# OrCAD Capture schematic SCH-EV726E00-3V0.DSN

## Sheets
1 Others: size C; title: EV726E00_Others; rev: 1.0; note: <Doc>
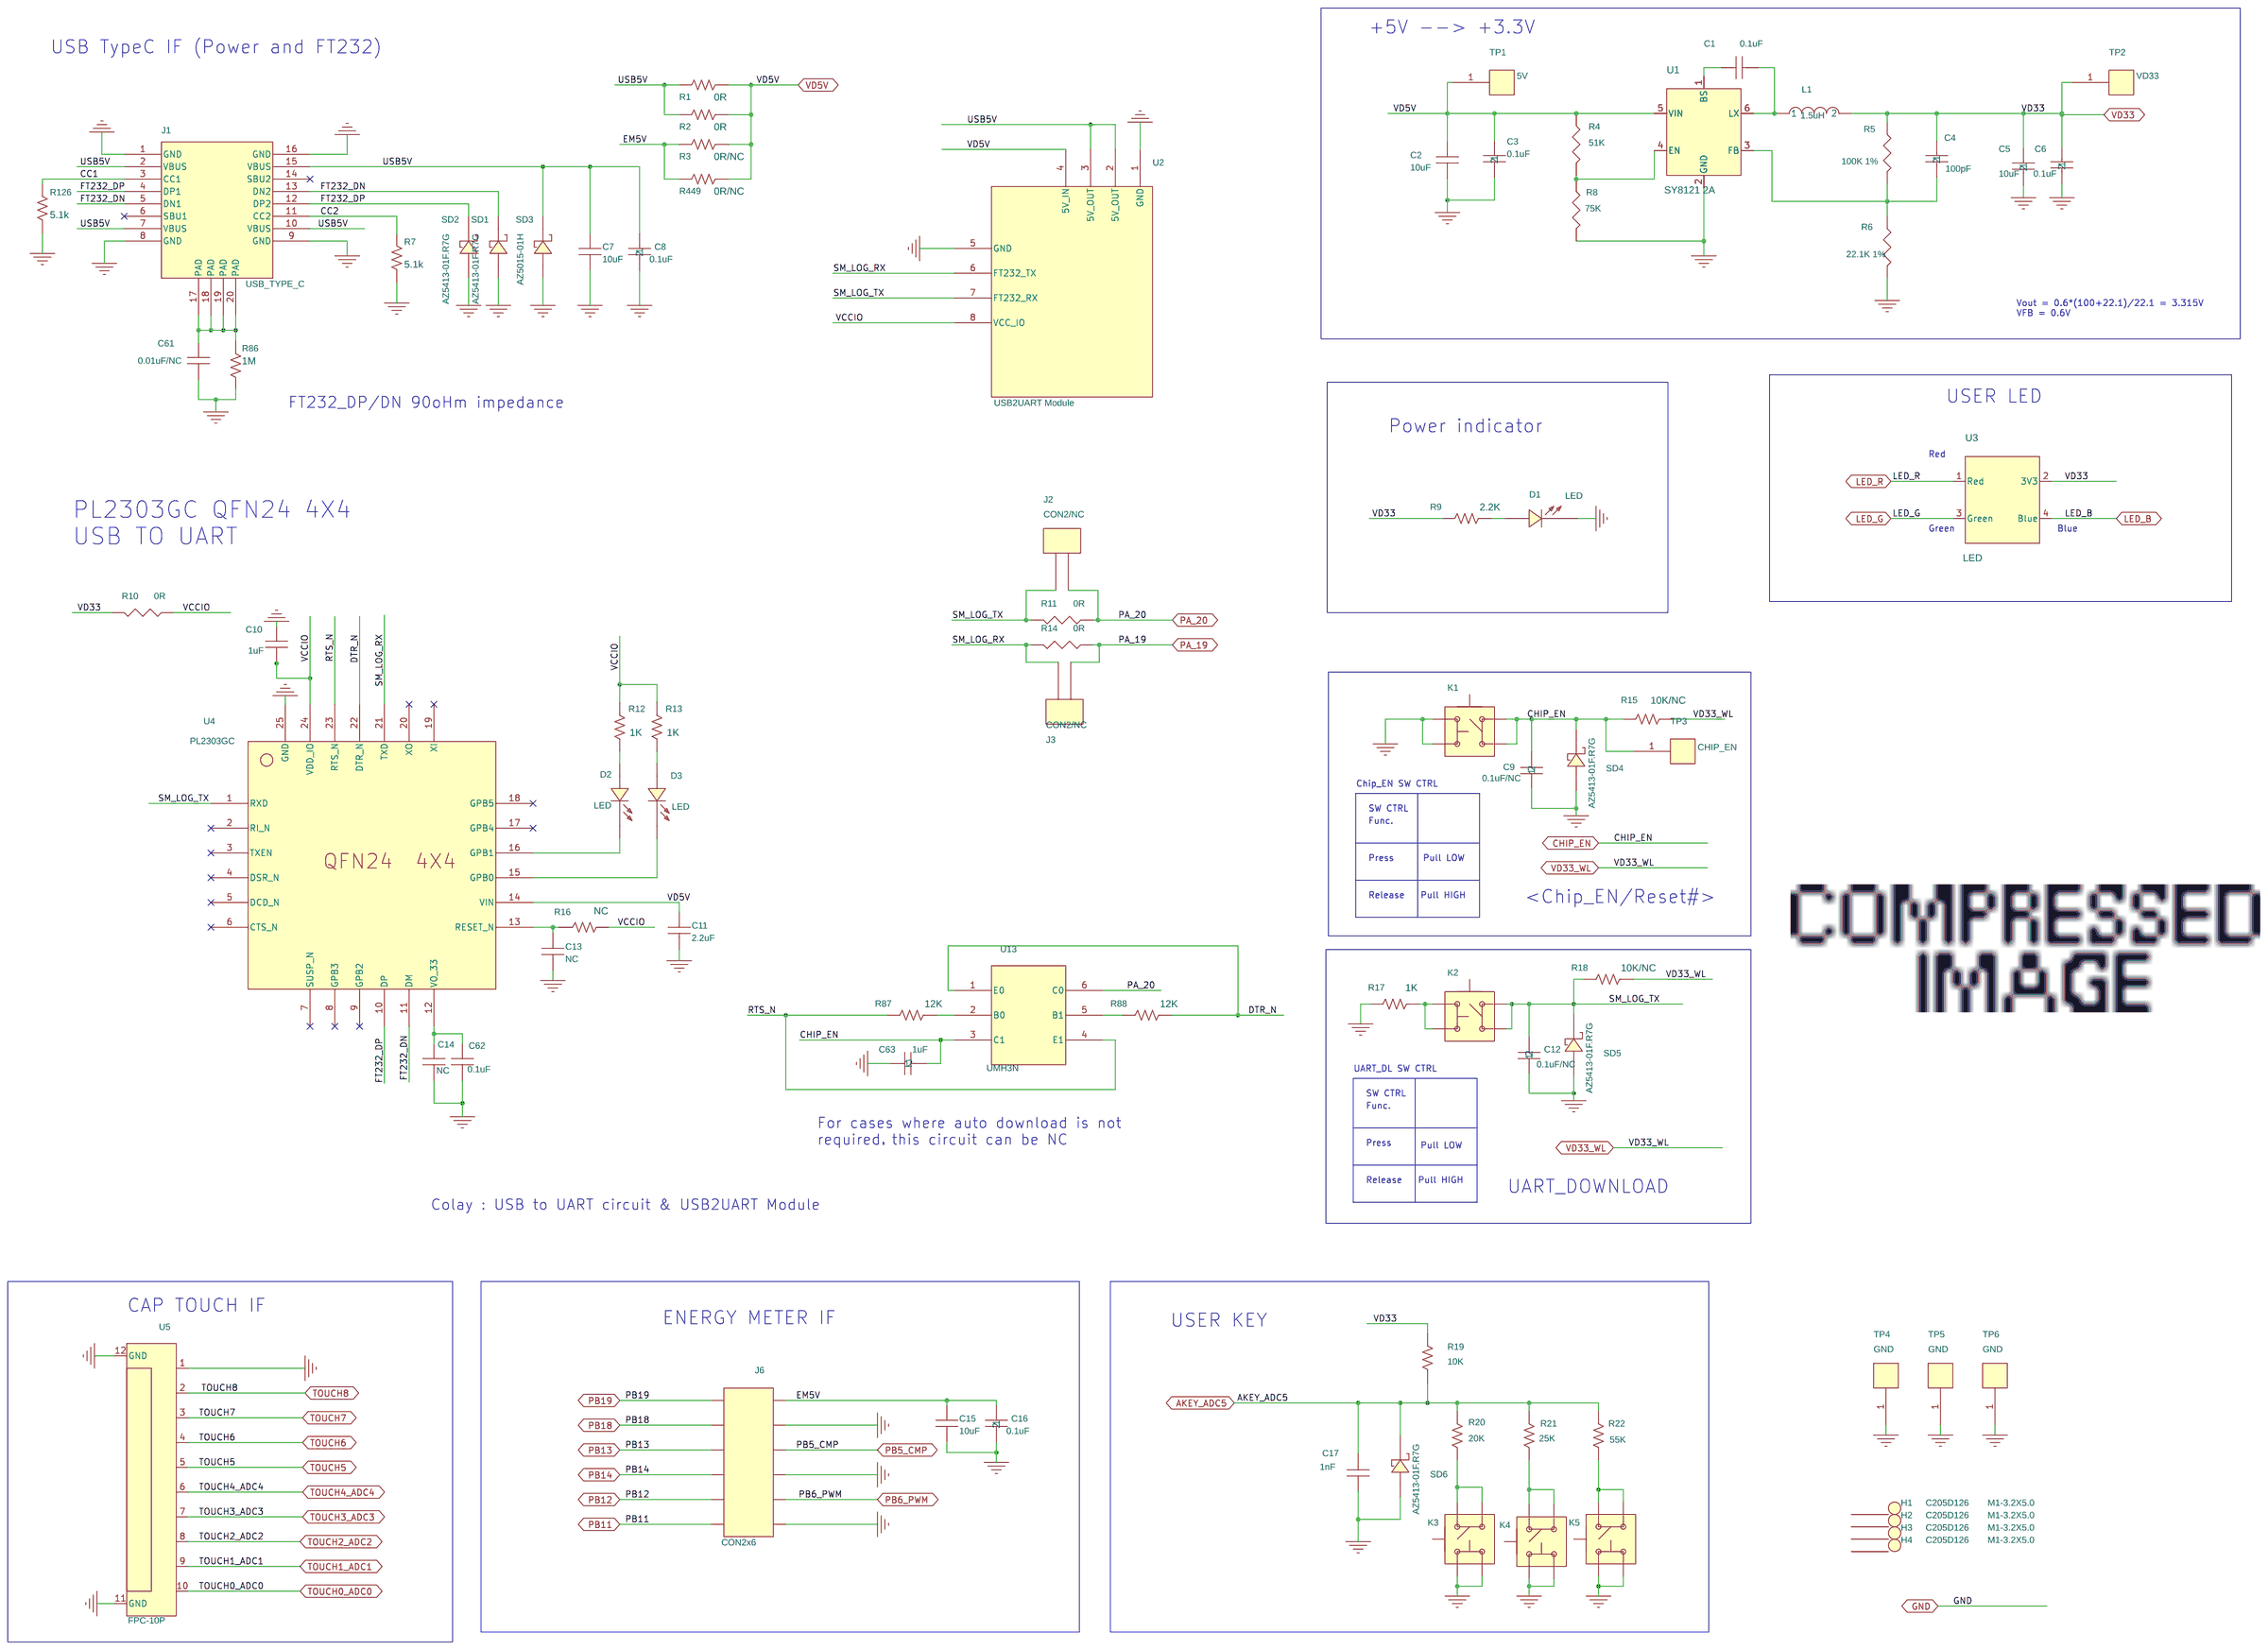
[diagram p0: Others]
2 SMPF: size C; title: EV726E00
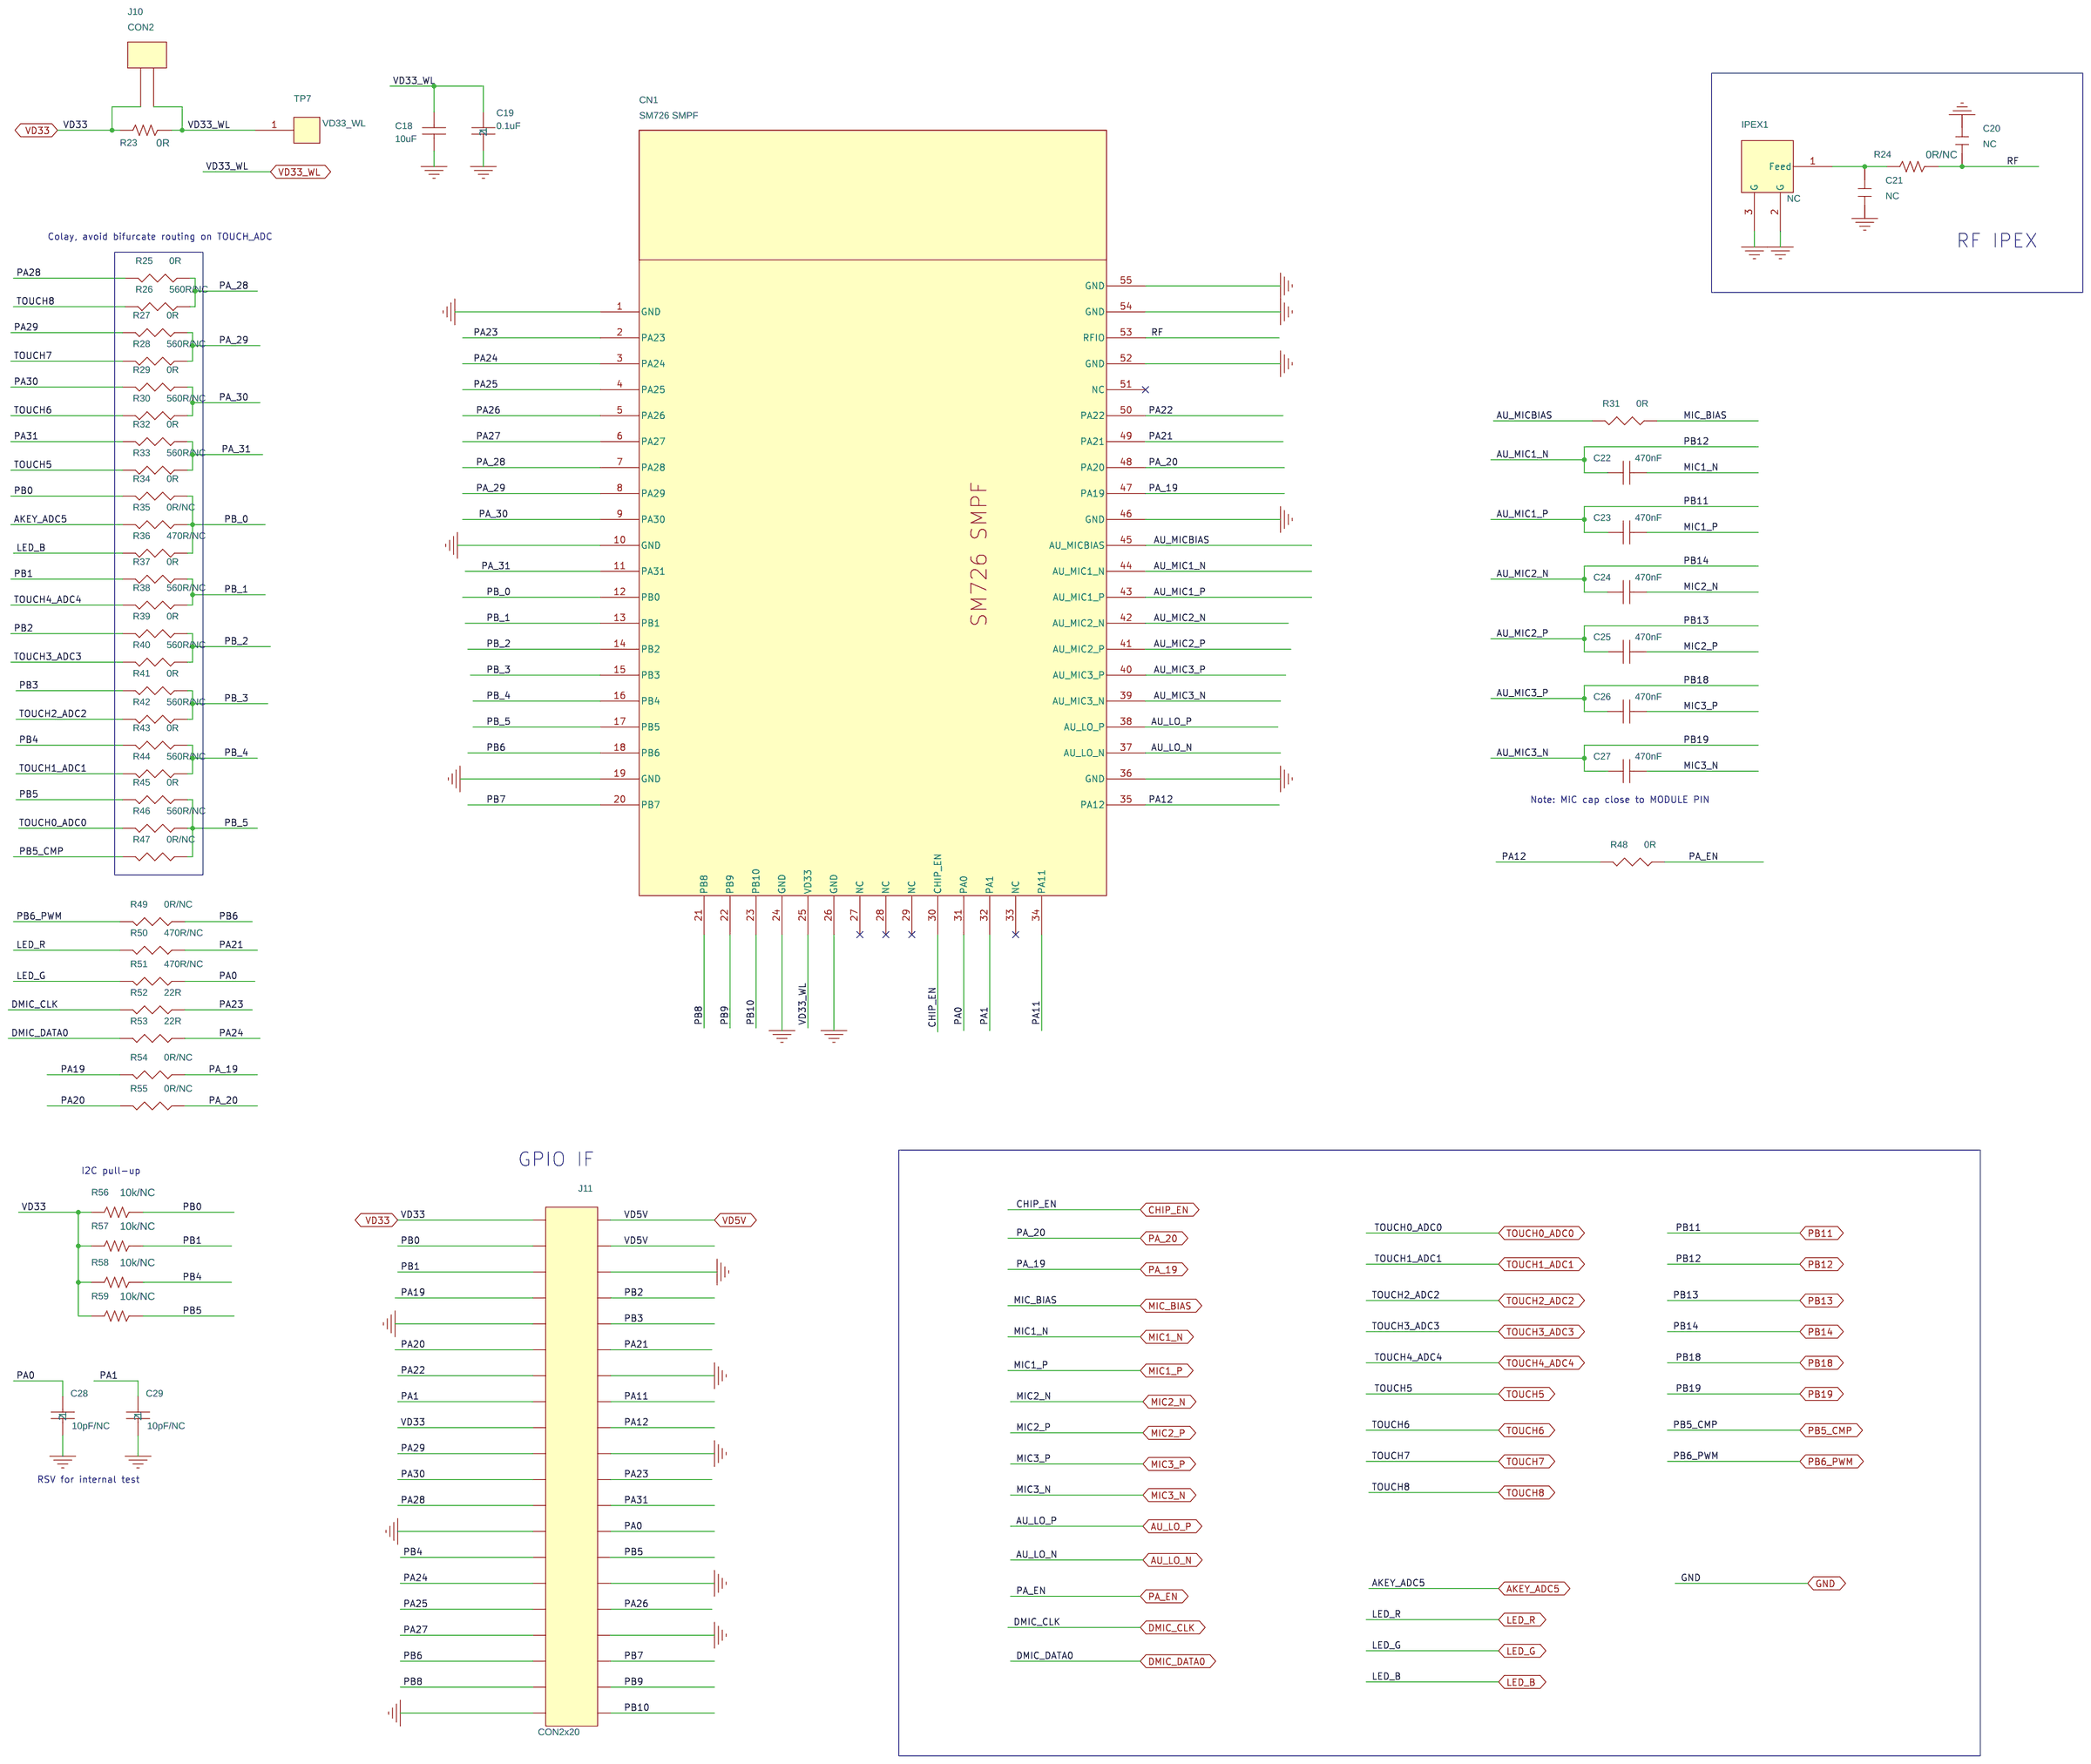
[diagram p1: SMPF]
3 Audio: size C; title: EV726E00_Audio
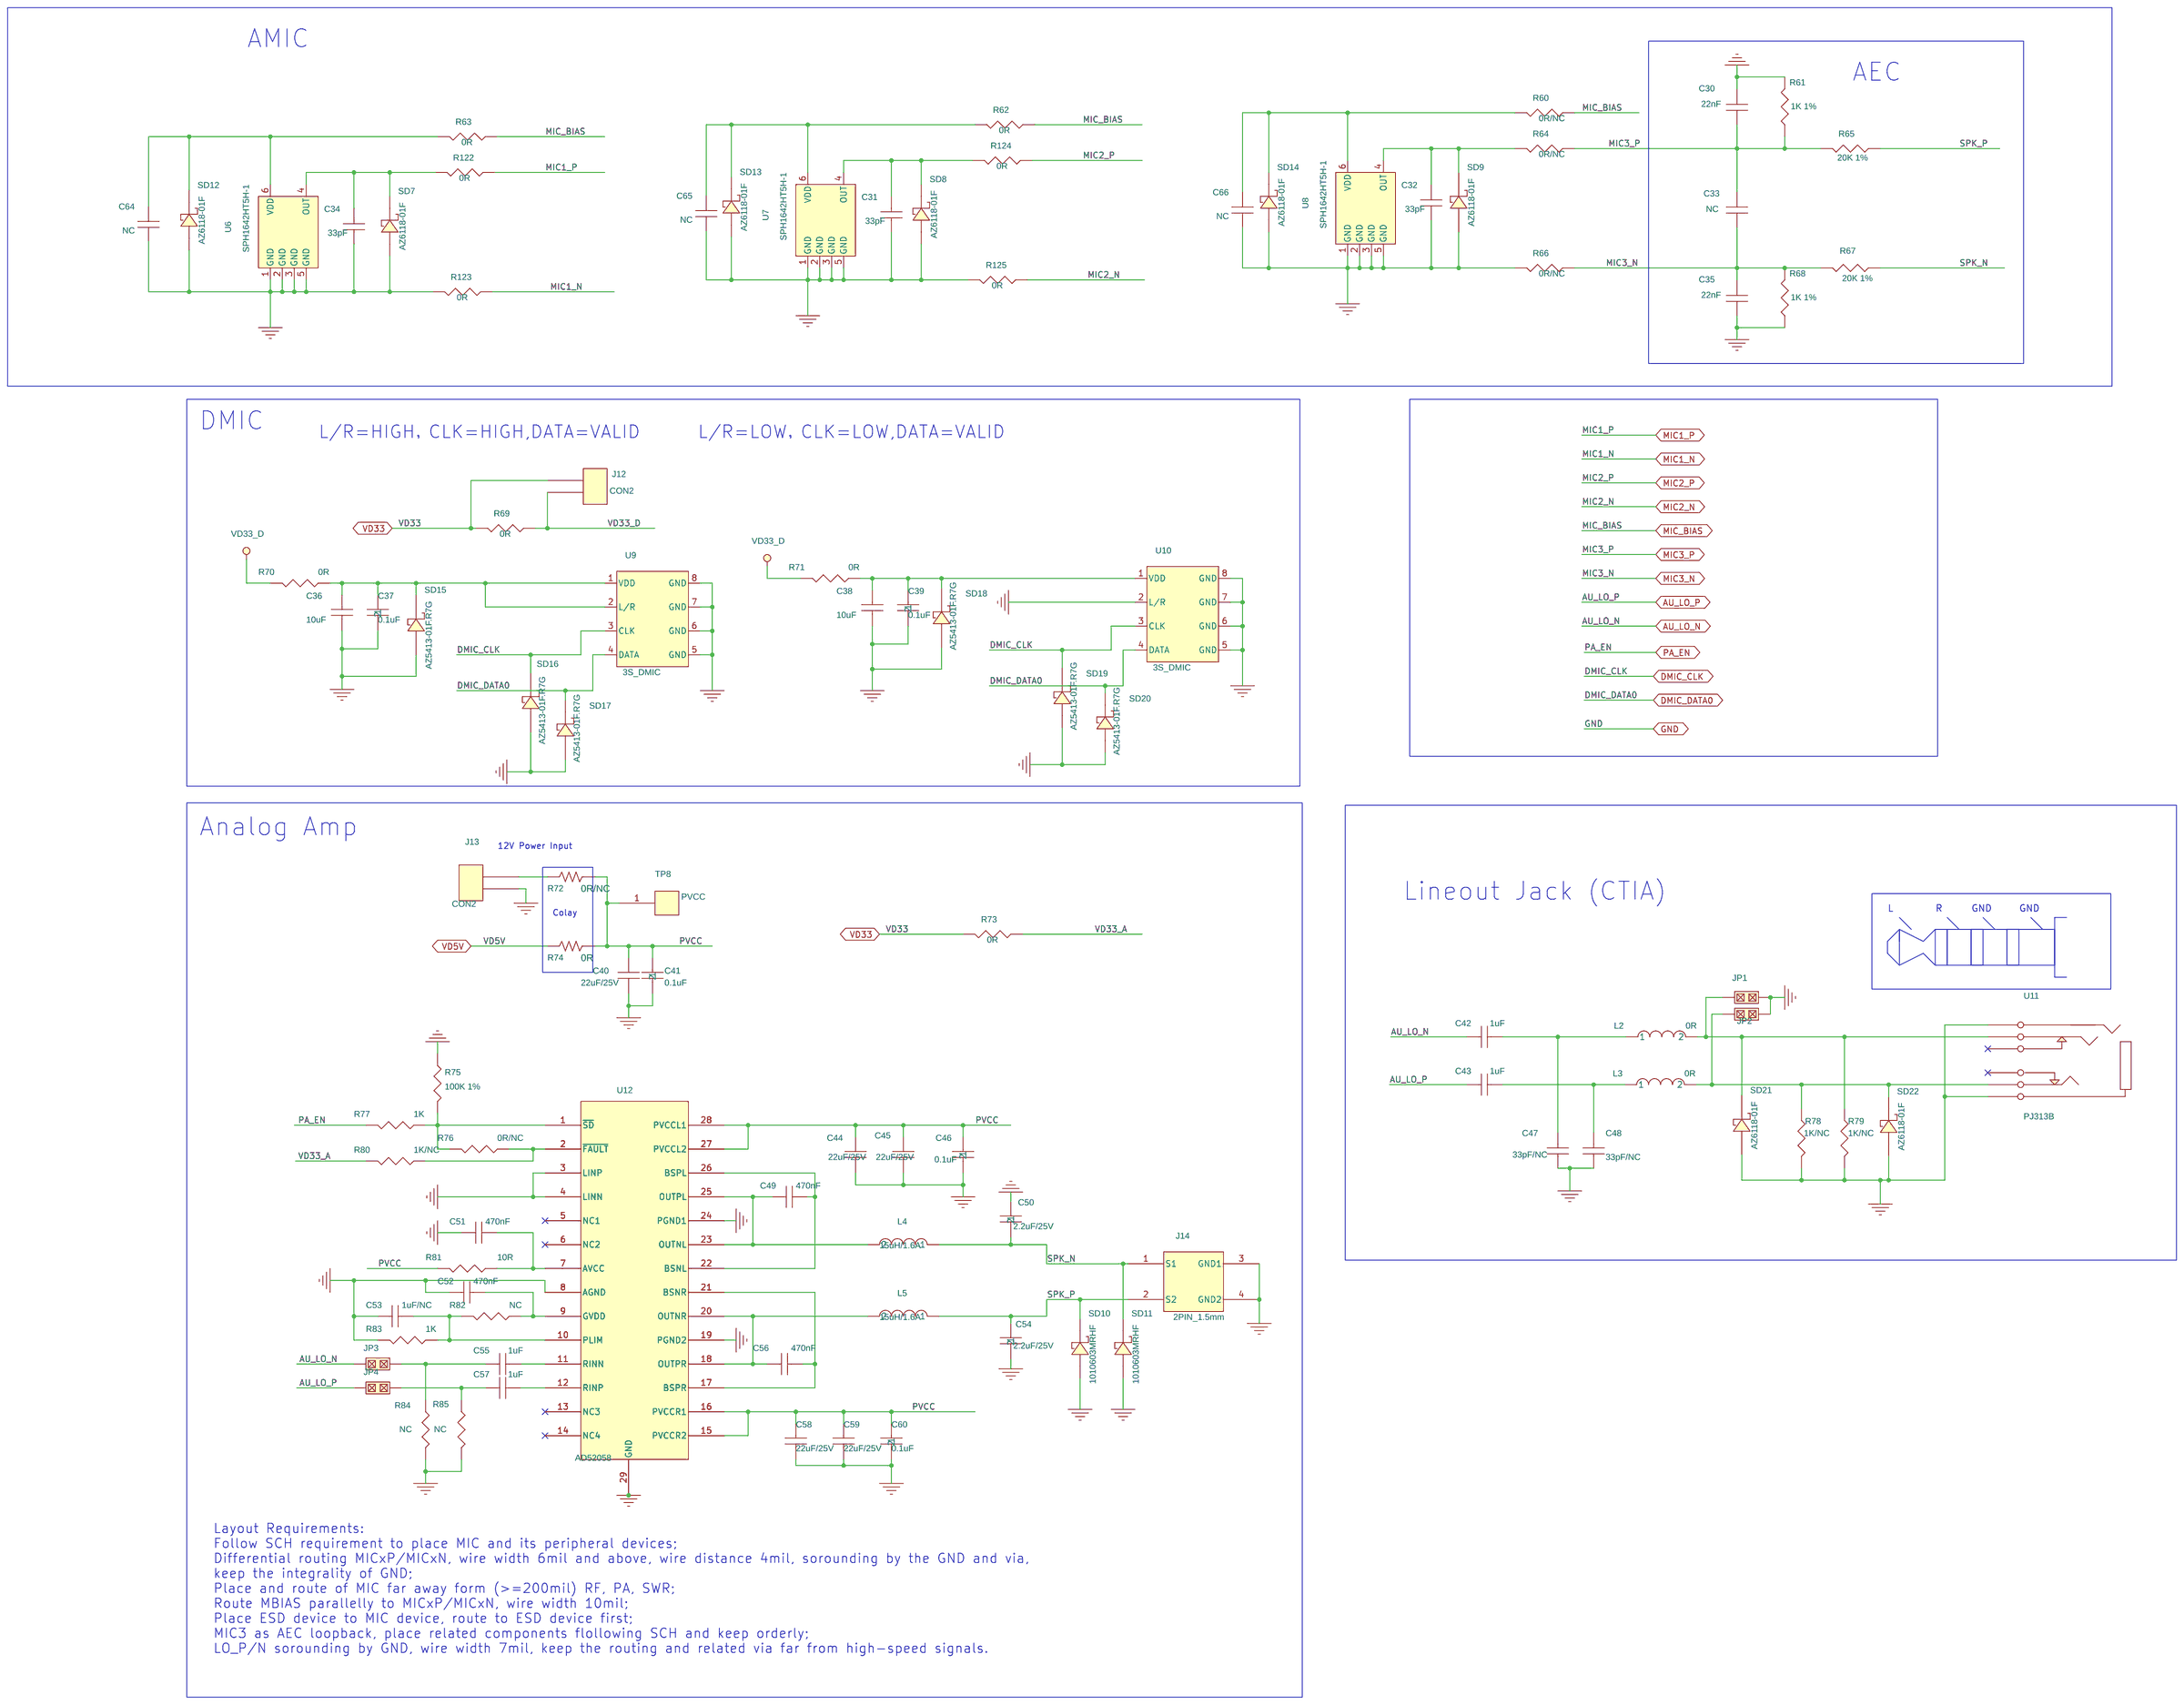
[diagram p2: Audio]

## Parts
sheet Audio
C30  22nF  [C0402]
C31  33pF  [C0402]
C32  33pF  [C0402]
C33  NC  [C0402]
C34  33pF  [C0402]
C35  22nF  [C0402]
C36  10uF  [C0603]
C37  0.1uF  [C0402]
C38  10uF  [C0603]
C39  0.1uF  [C0402]
C40  22uF/25V  [C0805]
C41  0.1uF  [C0402]
C42  1uF  [C0402]
C43  1uF  [C0402]
C44  22uF/25V  [C0805]
C45  22uF/25V  [C0805]
C46  0.1uF  [C0402]
C47  33pF/NC  [C0402]
C48  33pF/NC  [C0402]
C49  470nF  [C0402]
C50  2.2uF/25V  [C0402]
C51  470nF  [C0402]
C52  470nF  [C0402]
C53  1uF/NC  [C0402]
C54  2.2uF/25V  [C0402]
C55  1uF  [C0402]
C56  470nF  [C0402]
C57  1uF  [C0402]
C58  22uF/25V  [C0805]
C59  22uF/25V  [C0805]
C60  0.1uF  [C0402]
C64  NC  [C0402]
C65  NC  [C0402]
C66  NC  [C0402]
J12  CON2  [SIP2-2.54]
J13  CON2  [SIP2-2.54]
J14  2PIN_1.5mm  [2PIN-1.5MM]
JP1  1X2PIN  [SIP2-2.54]
JP2  1X2PIN  [SIP2-2.54]
JP3  1X2PIN  [SIP2-2.54]
JP4  1X2PIN  [SIP2-2.54]
L2  0R  [L0603]
L3  0R  [L0603]
L4  15uH/1.6A  [L5050]
L5  15uH/1.6A  [L5050]
R60  0R/NC  [R0402]
R61  1K 1%  [R0402]
R62  0R  [R0402]
R63  0R  [R0402]
R64  0R/NC  [R0402]
R65  20K 1%  [R0402]
R66  0R/NC  [R0402]
R67  20K 1%  [R0402]
R68  1K 1%  [R0402]
R69  0R  [R0402]
R70  0R  [R0402]
R71  0R  [R0402]
R72  0R/NC  [R0805]
R73  0R  [R0402]
R74  0R  [R0805]
R75  100K 1%  [R0402]
R76  0R/NC  [R0402]
R77  1K  [R0402]
R78  1K/NC  [R0402]
R79  1K/NC  [R0402]
R80  1K/NC  [R0402]
R81  10R  [R0402]
R82  NC  [R0402]
R83  1K  [R0402]
R84  NC  [R0402]
R85  NC  [R0402]
R122  0R  [R0402]
R123  0R  [R0402]
R124  0R  [R0402]
R125  0R  [R0402]
SD7  AZ6118-01F  [TVS-5413-6118-5451_DIR]
SD8  AZ6118-01F  [TVS-5413-6118-5451_DIR]
SD9  AZ6118-01F  [TVS-5413-6118-5451_DIR]
SD10  1010603MRHF  [TVS-5015-101060_DIR]
SD11  1010603MRHF  [TVS-5015-101060_DIR]
SD12  AZ6118-01F  [TVS-5413-6118-5451_DIR]
SD13  AZ6118-01F  [TVS-5413-6118-5451_DIR]
SD14  AZ6118-01F  [TVS-5413-6118-5451_DIR]
SD15  AZ5413-01F.R7G  [TVS-5413-6118-5451_DIR]
SD16  AZ5413-01F.R7G  [TVS-5413-6118-5451_DIR]
SD17  AZ5413-01F.R7G  [TVS-5413-6118-5451_DIR]
SD18  AZ5413-01F.R7G  [TVS-5413-6118-5451_DIR]
SD19  AZ5413-01F.R7G  [TVS-5413-6118-5451_DIR]
SD20  AZ5413-01F.R7G  [TVS-5413-6118-5451_DIR]
SD21  AZ6118-01F  [TVS-5413-6118-5451_DIR]
SD22  AZ6118-01F  [TVS-5413-6118-5451_DIR]
TP8  PVCC  [SIP-1P]
U6  SPH1642HT5H-1  [LGA]
U7  SPH1642HT5H-1  [LGA]
U8  SPH1642HT5H-1  [LGA]
U9  3S_DMIC  [3SM222FMT1KA]
U10  3S_DMIC  [3SM222FMT1KA]
U11  PJ313B  [AUDIO_JACK]
U12  AD52058  [E-TSSOP-28L]
sheet Others
C1  0.1uF  [C0402]
C2  10uF  [C0603]
C3  0.1uF  [C0402]
C4  100pF  [C0402]
C5  10uF  [C0603]
C6  0.1uF  [C0402]
C7  10uF  [C0603]
C8  0.1uF  [C0402]
C9  0.1uF/NC  [C0402]
C10  1uF  [C0402]
C11  2.2uF  [C0402]
C12  0.1uF/NC  [C0402]
C13  NC  [C0402]
C14  NC  [C0402]
C15  10uF  [C0603]
C16  0.1uF  [C0402]
C17  1nF  [C0402]
C61  0.01uF/NC  [C0402]
C62  0.1uF  [C0402]
C63  1uF  [C0603]
D1  LED  [LED-0603]
D2  LED  [LED-0603]
D3  LED  [LED-0603]
H1  C205D126  [M1-3.2X5.0]
H2  C205D126  [M1-3.2X5.0]
H3  C205D126  [M1-3.2X5.0]
H4  C205D126  [M1-3.2X5.0]
J1  USB_TYPE_C  [USB-C-SMT]
J2  CON2/NC  [SIP2-2.54]
J3  CON2/NC  [SIP2-2.54]
J6  CON2x6  [SIP6X2-2.54]
K1  Reset Button  [SW-4P-3X4]
K2  Reset Button  [SW-4P-3X4]
K3  Reset Button  [SW-4P-3X4]
K4  Reset Button  [SW-4P-3X4]
K5  Reset Button  [SW-4P-3X4]
L1  1.5uH  [MWSA0402]
R1  0R  [R0805]
R2  0R  [R0805]
R3  0R/NC  [R0805]
R4  51K  [R0402]
R5  100K 1%  [R0402]
R6  22.1K 1%  [R0402]
R7  5.1k  [R0402]
R8  75K  [R0402]
R9  2.2K  [R0402]
R10  0R  [R0402]
R11  0R  [R0402]
R12  1K  [R0402]
R13  1K  [R0402]
R14  0R  [R0402]
R15  10K/NC  [R0402]
R16  NC  [R0402]
R17  1K  [R0402]
R18  10K/NC  [R0402]
R19  10K  [R0402]
R20  20K  [R0402]
R21  25K  [R0402]
R22  55K  [R0402]
R86  1M  [R0402]
R87  12K  [R0402]
R88  12K  [R0402]
R126  5.1k  [R0402]
R449  0R/NC  [R0805]
SD1  AZ5413-01F.R7G  [TVS-5413-6118-5451_DIR]
SD2  AZ5413-01F.R7G  [TVS-5413-6118-5451_DIR]
SD3  AZ5015-01H  [TVS-5015-101060_DIR]
SD4  AZ5413-01F.R7G  [TVS-5413-6118-5451_DIR]
SD5  AZ5413-01F.R7G  [TVS-5413-6118-5451_DIR]
SD6  AZ5413-01F.R7G  [TVS-5413-6118-5451_DIR]
TP1  5V  [SIP-1P]
TP2  VD33  [SIP-1P]
TP3  CHIP_EN  [SIP-1P]
TP4  GND  [SIP-1P]
TP5  GND  [SIP-1P]
TP6  GND  [SIP-1P]
U1  SY8121 2A  [SOT-23-6]
U2  USB2UART Module  [MODULE_USB_FT232_2]
U3  LED  [LED3-3.5x2.8]
U4  PL2303GC  [UQFN24-4X4-PL2303GC]
U5  FPC-10P  [FPC-10-1mm]
U13  UMH3N  [SOT-363]
sheet SMPF
C18  10uF  [C0603]
C19  0.1uF  [C0402]
C20  NC  [C0402]
C21  NC  [C0402]
C22  470nF  [C0402]
C23  470nF  [C0402]
C24  470nF  [C0402]
C25  470nF  [C0402]
C26  470nF  [C0402]
C27  470nF  [C0402]
C28  10pF/NC  [C0402]
C29  10pF/NC  [C0402]
CN1  SM726 SMPF  [SM726E00_PF]
IPEX1  NC  [CON-IPEX]
J10  CON2  [SIP2-2.54]
J11  CON2x20  [SIP20X2-2.54]
R23  0R  [R0805]
R24  0R/NC  [R0402]
R25  0R  [R0402]
R26  560R/NC  [R0402]
R27  0R  [R0402]
R28  560R/NC  [R0402]
R29  0R  [R0402]
R30  560R/NC  [R0402]
R31  0R  [R0402]
R32  0R  [R0402]
R33  560R/NC  [R0402]
R34  0R  [R0402]
R35  0R/NC  [R0402]
R36  470R/NC  [R0402]
R37  0R  [R0402]
R38  560R/NC  [R0402]
R39  0R  [R0402]
R40  560R/NC  [R0402]
R41  0R  [R0402]
R42  560R/NC  [R0402]
R43  0R  [R0402]
R44  560R/NC  [R0402]
R45  0R  [R0402]
R46  560R/NC  [R0402]
R47  0R/NC  [R0402]
R48  0R  [R0402]
R49  0R/NC  [R0402]
R50  470R/NC  [R0402]
R51  470R/NC  [R0402]
R52  22R  [R0402]
R53  22R  [R0402]
R54  0R/NC  [R0402]
R55  0R/NC  [R0402]
R56  10k/NC  [R0402]
R57  10k/NC  [R0402]
R58  10k/NC  [R0402]
R59  10k/NC  [R0402]
TP7  VD33_WL  [SIP-1P]

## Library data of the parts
C30 = CAP_NP_9
C31 = CAP_NP_19
C17 C32 = CAP_NP_3
C33 = CAP_NP_21
C24 C34 = CAP_NP
C35 = CAP_NP_26
C36 = CAP_NP_1: Y5V, ∮20%, 6.3; Manufacturer: WALSIN; Part Number: 0805F226Z6R3CT; Unit Price(USD): 0.01921
C5 C29 C37 = C_2: X7R, ∮10%, 10V; Manufacturer: WALSIN; Part Number: 0402B104K100CT; Unit Price(USD): 0.0008
C38 = CAP_NP_22: Y5V, ∮20%, 6.3; Manufacturer: WALSIN; Part Number: 0805F226Z6R3CT; Unit Price(USD): 0.01921
C9 C28 C39 C63 = C_1: X7R, ∮10%, 10V; Manufacturer: WALSIN; Part Number: 0402B104K100CT; Unit Price(USD): 0.0008
C40 = CAP_NP_13: Y5V, ∮20%, 6.3; Manufacturer: WALSIN; Part Number: 0805F226Z6R3CT; Unit Price(USD): 0.01921
C4 C41 = C_3: X7R, ∮10%, 10V; Manufacturer: WALSIN; Part Number: 0402B104K100CT; Unit Price(USD): 0.0008
C42 = CAP_NP_25
C43 = CAP_NP_12
C44 = CAP_NP_24: Y5V, ∮20%, 6.3; Manufacturer: WALSIN; Part Number: 0805F226Z6R3CT; Unit Price(USD): 0.01921
C45 = CAP_NP_17: Y5V, ∮20%, 6.3; Manufacturer: WALSIN; Part Number: 0805F226Z6R3CT; Unit Price(USD): 0.01921
C16 C46 = C_4: X7R, ∮10%, 10V; Manufacturer: WALSIN; Part Number: 0402B104K100CT; Unit Price(USD): 0.0008
C47 = CAP_NP_15
C48 = CAP_NP_18
C49 = CAP_NP_23
C6 C50 = C_5: X7R, ∮10%, 10V; Manufacturer: WALSIN; Part Number: 0402B104K100CT; Unit Price(USD): 0.0008
C51 = CAP_NP_14
C26 C52 = CAP_NP_4
C23 C53 = CAP_NP_6
C3 C54 = C_6: X7R, ∮10%, 10V; Manufacturer: WALSIN; Part Number: 0402B104K100CT; Unit Price(USD): 0.0008
C55 = CAP_NP_11
C56 = CAP_NP_7
C57 = CAP_NP_20
C58 = CAP_NP_16: Y5V, ∮20%, 6.3; Manufacturer: WALSIN; Part Number: 0805F226Z6R3CT; Unit Price(USD): 0.01921
C15 C59 = CAP_NP_8: Y5V, ∮20%, 6.3; Manufacturer: WALSIN; Part Number: 0805F226Z6R3CT; Unit Price(USD): 0.01921
C8 C19 C60 = C: X7R, ∮10%, 10V; Manufacturer: WALSIN; Part Number: 0402B104K100CT; Unit Price(USD): 0.0008
C25 C64 = CAP_NP_2
C22 C65 = CAP_NP_5
C66 = CAP_NP_10
J2 J3 J10 J12 J13 = CON2
J14 = 2PIN_1.5mm
JP1-JP4 = 1X2PIN
L2 = INDUCTOR_3
L1 L3 = INDUCTOR
L4 = INDUCTOR_1
L5 = INDUCTOR_2
R10 R11 R14 R25-R55 R60-R71 R73 R75-R85 R122-R125 = R_v2
R1-R3 R9 R12 R13 R16 R23 R72 R74 R86-R88 R449 = RES_V: Manufacturer: WALSIN; Part Number: WR04X4700FTL; Unit Price(USD): 0.00032
SD1-SD22 = DIODE_SCHOTTKY_2
TP1-TP8 = TP
U6-U8 = SPH1642HT5H-1_3
U9 U10 = 3S_DMIC_2
U11 = PJ313B
U12 = AD52066_3
C1 = CAP_NP_10: Y5V, ∮20%, 25V; Manufacturer: WALSIN; Part Number: 0603F104Z250CT; Unit Price(USD): 0.00118
C2 = CAP_NP: Y5V, ∮20%, 6.3; Manufacturer: WALSIN; Part Number: 0805F226Z6R3CT; Unit Price(USD): 0.01921
C7 = CAP_NP_4: Y5V, ∮20%, 6.3; Manufacturer: WALSIN; Part Number: 0805F226Z6R3CT; Unit Price(USD): 0.01921
C10 = CAP_NP_2: NPO, ∮10%, 50V; Manufacturer: WALSIN; Part Number: 0402B102K500CT; Unit Price(USD): 0.00076
C11 = CAP_NP_1: NPO, ∮10%, 50V; Manufacturer: WALSIN; Part Number: 0402B102K500CT; Unit Price(USD): 0.00076
C12 = C_7: X7R, ∮10%, 10V; Manufacturer: WALSIN; Part Number: 0402B104K100CT; Unit Price(USD): 0.0008
C13 = CAP_NP_5: NPO, ∮10%, 50V; Manufacturer: WALSIN; Part Number: 0402B102K500CT; Unit Price(USD): 0.00076
C14 = CAP_NP_7: NPO, ∮10%, 50V; Manufacturer: WALSIN; Part Number: 0402B102K500CT; Unit Price(USD): 0.00076
C61 = CAP_NP_6: NPO, ∮10%, 50V; Manufacturer: WALSIN; Part Number: 0402B102K500CT; Unit Price(USD): 0.00076
C62 = CAP_NP_9: NPO, ∮10%, 50V; Manufacturer: WALSIN; Part Number: 0402B102K500CT; Unit Price(USD): 0.00076
D1-D3 = LED_0
H1-H4 = HOLE_PTH: FOR PEGATRON ENTEK; Colay_Alternate: N/A; Colay_Group: N/A; Component_Name: TOOLING HOLE C205D126; Data_Sheet: K:\DataSheet\13-MECHANICAL\T-SH00002166.zip; Device: hole_c205d126; Modify_data: 2013/01/17; Optional: N/A; Package_Type: DIP; Part Number: T-SH00002166; Part Type: 13MECHANICAL\HOLE; Subsystem_ID: N/A
J1 = USB_TYPE_C: Manufacturer: Molex; Part Number: 2171790001
J6 = CON6_5
K1-K5 = BUTTON_(RST)_2: Part Number: TAVPCM01-038ST-R
R4-R6 R8 = RESISTOR
R7 R126 = RES_V: Manufacturer: WALSIN; Part Number: WR04X1002FTL; Unit Price(USD): 0.00032
R15 R17 R18 R24 R56-R59 = RES_V: Manufacturer: WALSIN; Part Number: WR04X1003FTL; Unit Price(USD): 0.00032
R19-R22 = R
U1 = CAT7103_0: ID: A
U2 = USB2UART_0
U3 = CAT7103_1: ID: A
U4 = RL5760_4
U5 = FPC-10P
U13 = LT1084-3_3.3
C18 = CAP_NP_3: Y5V, ∮20%, 6.3; Manufacturer: WALSIN; Part Number: 0805F226Z6R3CT; Unit Price(USD): 0.01921
C20 C21 = C_402
C27 = CAP_NP_1
CN1 = R0402_23.06K_WALSIN
IPEX1 = TP_0
J11 = CON6_2

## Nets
GND: C2.2 C3.2 C5.2 C6.2 C7.2 C8.2 C9.1 C10.1 C11.2 C12.1 C13.2 C14.2 C15.2 C16.2 C17.1 C18.2 C19.2 C20.2 C21.1 C28.2 C29.2 C30.2 C31.1 C32.1 C34.1 C35.1 C36.2 C37.2 C38.2 C39.2 C40.2 C41.2 C44.2 C45.2 C46.2 C47.1 C48.1 C50.1 C51.1 C52.1 C53.1 C54.2 C58.2 C59.2 C60.2 C61.2 C62.2 C63.1 C64.1 C65.1 C66.1 CN1.1(GND) CN1.10(GND) CN1.19(GND) CN1.24(GND) CN1.26(GND) CN1.36(GND) CN1.46(GND) CN1.52(GND) CN1.54(GND) CN1.55(GND) D1.2 IPEX1.2(G) IPEX1.3(G) J1.1(GND) J1.8(GND) J1.9(GND) J1.16(GND) J6.4 J6.8 J6.12 J11.6 J11.9 J11.14 J11.20 J11.25 J11.30 J11.34 J11.39 J13.2 J14.3(GND1) J14.4(GND2) JP1.2 JP2.2 K1.3 K1.4 K3.3 K3.4 K4.3 K4.4 K5.3 K5.4 R6.2 R7.2 R8.2 R17.1 R61.2 R66.2 R68.1 R75.1 R78.2 R79.2 R83.2 R84.1 R85.1 R86.1 R123.2 R125.2 R126.2 SD1.2 SD2.2 SD3.2 SD4.2 SD5.2 SD6.2 SD7.2 SD8.2 SD9.2 SD10.2 SD11.2 SD12.2 SD13.2 SD14.2 SD15.2 SD16.2 SD17.2 SD18.2 SD19.2 SD20.2 SD21.2 SD22.2 TP4.1 TP5.1 TP6.1 U1.2(GND) U2.1(GND) U2.5(GND) U4.25(GND) U5.1 U5.11(GND) U5.12(GND) U6.1(GND) U6.2(GND) U6.3(GND) U6.5(GND) U7.1(GND) U7.2(GND) U7.3(GND) U7.5(GND) U8.1(GND) U8.2(GND) U8.3(GND) U8.5(GND) U9.5(GND) U9.6(GND) U9.7(GND) U9.8(GND) U10.2(L/R) U10.5(GND) U10.6(GND) U10.7(GND) U10.8(GND) U11.1 U11.2 U12.3(LINP) U12.4(LINN) U12.8(AGND) U12.19(PGND2) U12.24(PGND1) U12.29(GND)
PVCC: C40.1 C41.1 C44.1 C45.1 C46.1 C58.1 C59.1 C60.1 R72.2 R74.2 R81.2 TP8.1 U12.15(PVCCR2) U12.16(PVCCR1) U12.27(PVCCL2) U12.28(PVCCL1)
VCCIO: C10.2 R10.1 R12.2 R13.2 R16.1 U2.8(VCC_IO) U4.24(VDD_IO)
AKEY_ADC5: C17.2 R19.1 R20.1 R21.1 R22.1 R35.2 SD6.1
AU_LO_N: C42.1 CN1.37(AU_LO_N) JP3.1
AU_LO_P: C43.1 CN1.38(AU_LO_P) JP4.1
AU_MICBIAS: CN1.45(AU_MICBIAS) R31.2
CC1: J1.3(CC1) R126.1
CC2: J1.11(CC2) R7.1
CHIP_EN: C9.2 C63.2 CN1.30(CHIP_EN) K1.1 K1.2 R15.1 SD4.1 TP3.1 U13.3(C1)
DMIC_CLK: R52.2 SD16.1 SD19.1 U9.3(CLK) U10.3(CLK)
DMIC_DATA0: R53.2 SD17.1 SD20.1 U9.4(DATA) U10.4(DATA)
DTR_N: R88.2 U4.22(DTR_N) U13.1(E0)
EM5V: C15.1 C16.1 J6.2 R3.1 R449.1
FT232_DN: J1.5(DN1) J1.13(DN2) SD1.1 U4.11(DM)
FT232_DP: J1.4(DP1) J1.12(DP2) SD2.1 U4.10(DP)
LED_B: R36.2 U3.4(Blue)
LED_G: R51.2 U3.3(Green)
LED_R: R50.2 U3.1(Red)
MIC1_N: C22.2 R123.1
MIC1_P: C23.2 R122.1
MIC2_N: C24.2 R125.1
MIC2_P: C25.2 R124.1
MIC3_N: C27.2 C33.1 C35.2 R66.1 R67.2 R68.2
MIC3_P: C26.2 C30.1 C33.2 R61.1 R64.1 R65.2
MIC_BIAS: R31.1 R60.1 R62.1 R63.1
PA0: C28.1 CN1.31(PA0) J11.26 R51.1
PA1: C29.1 CN1.32(PA1) J11.15
PA11: CN1.34(PA11) J11.16
PA12: CN1.35(PA12) J11.18 R48.2
PA19: J11.7 R54.2
PA20: J11.11 R55.2
PA21: CN1.49(PA21) J11.12 R50.1
PA22: CN1.50(PA22) J11.13
PA23: CN1.2(PA23) J11.22 R52.1
PA24: CN1.3(PA24) J11.29 R53.1
PA25: CN1.4(PA25) J11.31
PA26: CN1.5(PA26) J11.32
PA27: CN1.6(PA27) J11.33
PA28: J11.23 R25.2
PA29: J11.19 R27.2
PA30: J11.21 R29.2
PA31: J11.24 R32.2
PA_19: CN1.47(PA19) J3.2 R14.1 R54.1
PA_20: CN1.48(PA20) J2.2 R11.1 R55.1 U13.6(C0)
PA_28: CN1.7(PA28) R25.1 R26.1
PA_29: CN1.8(PA29) R27.1 R28.1
PA_30: CN1.9(PA30) R29.1 R30.1
PA_31: CN1.11(PA31) R32.1 R33.1
PA_EN: R48.1 R77.2
PB0: J11.3 R34.2 R56.2
PB1: J11.5 R37.2 R57.2
PB2: J11.8 R39.2
PB3: J11.10 R41.2
PB4: J11.27 R43.2 R58.2
PB5: J11.28 R45.2 R59.2
PB5_CMP: J6.6 R47.2
PB6: CN1.18(PB6) J11.35 R49.1
PB6_PWM: J6.10 R49.2
PB7: CN1.20(PB7) J11.36
PB8: CN1.21(PB8) J11.37
PB9: CN1.22(PB9) J11.38
PB10: CN1.23(PB10) J11.40
PB11: C23.1 CN1.43(AU_MIC1_P) J6.11
PB12: C22.1 CN1.44(AU_MIC1_N) J6.9
PB13: C25.1 CN1.41(AU_MIC2_P) J6.5
PB14: C24.1 CN1.42(AU_MIC2_N) J6.7
PB18: C26.1 CN1.40(AU_MIC3_P) J6.3
PB19: C27.1 CN1.39(AU_MIC3_N) J6.1
PB_0: CN1.12(PB0) R34.1 R35.1 R36.1
PB_1: CN1.13(PB1) R37.1 R38.1
PB_2: CN1.14(PB2) R39.1 R40.1
PB_3: CN1.15(PB3) R41.1 R42.1
PB_4: CN1.16(PB4) R43.1 R44.1
PB_5: CN1.17(PB5) R45.1 R46.1 R47.1
RF: C20.1 CN1.53(RFIO) R24.2
RTS_N: R87.1 U4.23(RTS_N) U13.4(E1)
SM_LOG_RX: J3.1 R14.2 U2.6(FT232_TX) U4.21(TXD)
SM_LOG_TX: C12.2 J2.1 K2.1 K2.2 R11.2 R18.1 SD5.1 U2.7(FT232_RX) U4.1(RXD)
SPK_N: C50.2 J14.1(S1) L4.1 R67.1 SD11.1
SPK_P: C54.1 J14.2(S2) L5.1 R65.1 SD10.1
TOUCH0_ADC0: R46.2 U5.10
TOUCH1_ADC1: R44.2 U5.9
TOUCH2_ADC2: R42.2 U5.8
TOUCH3_ADC3: R40.2 U5.7
TOUCH4_ADC4: R38.2 U5.6
TOUCH5: R33.2 U5.5
TOUCH6: R30.2 U5.4
TOUCH7: R28.2 U5.3
TOUCH8: R26.2 U5.2
USB5V: C7.1 C8.1 J1.2(VBUS) J1.7(VBUS) J1.10(VBUS) J1.15(VBUS) R1.1 R2.1 SD3.1 U2.2(5V_OUT) U2.3(5V_OUT)
VD5V: C2.1 C3.1 C11.1 J11.2 J11.4 R1.2 R2.2 R3.2 R4.1 R74.1 R449.2 TP1.1 U1.5(VIN) U2.4(5V_IN) U4.14(VIN)
VD33: C4.1 C5.1 C6.1 J10.1 J11.1 J11.17 J12.1 L1.2 R5.1 R9.1 R10.2 R19.2 R23.1 R56.1 R57.1 R58.1 R59.1 R69.2 R73.2 TP2.1 U3.2(3V3)
VD33_A: R73.1 R80.2
VD33_D: J12.2 R69.1 R70.2 R71.2
VD33_WL: C18.1 C19.1 CN1.25(VD33) J10.2 R15.2 R18.2 R23.2 TP7.1
N16636749: D1.1 R9.2
N16756983: C21.2 IPEX1.1(Feed) R24.1
N16771558: C36.1 C37.1 R70.1 SD15.1 U9.1(VDD) U9.2(L/R)
N16771674: C64.2 R63.2 SD12.1 U6.6(VDD)
N16771904: C38.1 C39.1 R71.1 SD18.1 U10.1(VDD)
N16772206: C34.2 R122.2 SD7.1 U6.4(OUT)
N16773556: C65.2 R62.2 SD13.1 U7.6(VDD)
N16773676: C31.2 R124.2 SD8.1 U7.4(OUT)
N16775926: C52.2 R82.1 U12.9(GVDD)
N16775938: C57.1 JP4.2 R85.2
N16775946: C53.2 R82.2 R83.1 U12.10(PLIM)
N16776024: R75.2 R76.2 R77.1 U12.1(~{SD})
N16776050: R76.1 R80.1 U12.2(~{FAULT})
N16776088: C55.2 U12.11(RINN)
N16776110: C49.1 L4.2 U12.23(OUTNL) U12.25(OUTPL)
N16776122: C56.2 U12.17(BSPR) U12.21(BSNR)
N16776142: C56.1 L5.2 U12.18(OUTPR) U12.20(OUTNR)
N16776236: C49.2 U12.22(BSNL) U12.26(BSPL)
N16776446: C51.2 R81.1 U12.7(AVCC)
N16776562: C55.1 JP3.2 R84.2
N16776924: C57.2 U12.12(RINP)
N16830629: J13.1 R72.1
N16831666: JP2.1 L3.2 R78.1 SD22.1 U11.4
N16831681: JP1.1 L2.2 R79.1 SD21.1 U11.3
N16831824: C42.2 C47.2 L2.1
N16831856: C43.2 C48.2 L3.1
N16836743: C32.2 R64.2 SD9.1 U8.4(OUT)
N16836759: C66.2 R60.2 SD14.1 U8.6(VDD)
N16864478: K3.1 K3.2 R20.2
N16868334: K4.1 K4.2 R21.2
N16868337: K5.1 K5.2 R22.2
N16895641: C61.1 J1.17(PAD) J1.18(PAD) J1.19(PAD) J1.20(PAD) R86.2
N16896520: C4.2 R5.2 R6.1 U1.3(FB)
N16896557: R4.2 R8.1 U1.4(EN)
N16896631: C1.2 L1.1 U1.6(LX)
N16896691: C1.1 U1.1(BS)
N16912656: K2.3 K2.4 R17.2
N16939033: C13.1 R16.2 U4.13(RESET_N)
N16939064: D2.1 R12.1
N16939066: D2.2 U4.16(GPB1)
N16939120: D3.1 R13.1
N16939124: D3.2 U4.15(GPB0)
N16939155: C14.1 C62.1 U4.12(VO_33)
N16939526: R88.1 U13.5(B1)
N16939528: R87.2 U13.2(B0)

Not connected (* = marked no-connect by the designer): CN1 27(NC)* 28(NC)* 29(NC)* 33(NC)* 51(NC)*; H1 1; H2 1; H3 1; H4 1; J1 6(SBU1)* 14(SBU2)*; U4 2(RI_N)* 3(TXEN)* 4(DSR_N)* 5(DCD_N)* 6(CTS_N)* 7(SUSP_N)* 8(GPB3)* 9(GPB2)* 17(GPB4)* 18(GPB5)* 19(XI)* 20(XO)*; U11 5* 6*; U12 5(NC1)* 6(NC2)* 13(NC3)* 14(NC4)*

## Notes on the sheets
sheet 1
- +5V --> +3.3V
- USB TypeC IF (Power and FT232)
- Vout = 0.6*(100+22.1)/22.1 = 3.315V
  VFB = 0.6V
- FT232_DP/DN 90oHm impedance
- USER LED
- Power indicator
- Red
- PL2303GC QFN24 4X4
  USB TO UART
- Green
- Blue
- Chip_EN SW CTRL
- SW CTRL
- Func.
- Press
- Pull LOW
- Release
- Pull HIGH
- <Chip_EN/Reset#>
- UART_DL SW CTRL
- Func.
- SW CTRL
- For cases where auto download is not
  required，this circuit can be NC
- Press
- Pull LOW
- Release
- Pull HIGH
- UART_DOWNLOAD
- Colay : USB to UART circuit & USB2UART Module
- CAP TOUCH IF
- ENERGY METER IF
- USER KEY
sheet 2
- Colay, avoid bifurcate routing on TOUCH_ADC
- RF IPEX
- Note: MIC cap close to MODULE PIN
- GPIO IF
- I2C pull-up
- RSV for internal test
sheet 3
- AMIC
- AEC
- DMIC
- L/R=HIGH，CLK=HIGH,DATA=VALID      L/R=LOW，CLK=LOW,DATA=VALID
- Analog Amp
- 12V Power Input
- Lineout Jack (CTIA)
- L
- R
- GND
- GND
- Colay
- Layout Requirements:
  Follow SCH requirement to place MIC and its peripheral devices;
  Differential routing MICxP/MICxN, wire width 6mil and above, wire distance 4mil, sorounding by the GND and via,
  keep the integrality of GND;
  Place and route of MIC far away form (>=200mil) RF, PA, SWR;
  Route MBIAS parallelly to MICxP/MICxN, wire width 10mil;
  Place ESD device to MIC device, route to ESD device first;
  MIC3 as AEC loopback, place related components flollowing SCH and keep orderly;
  LO_P/N sorounding by GND, wire width 7mil, keep the routing and related via far from high-speed signals.
